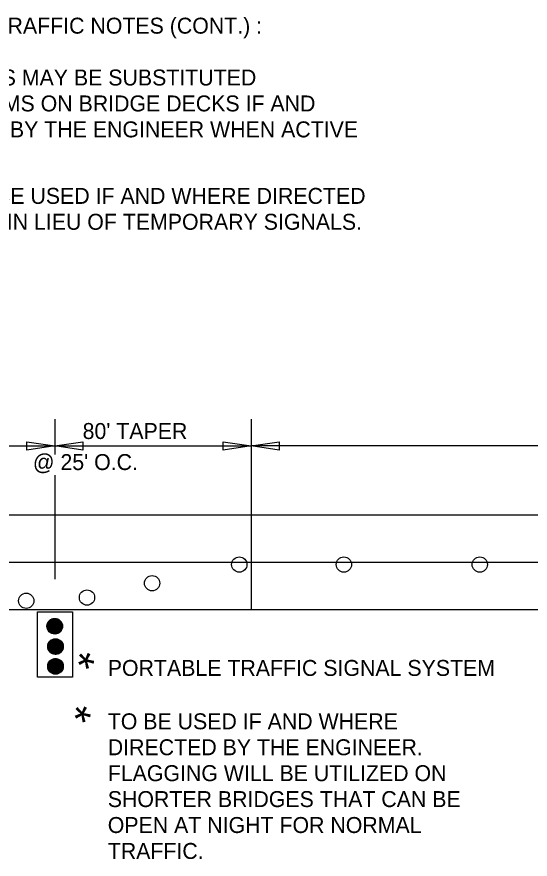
# Model space of a CAD drawing. Extents: x 1927831 to 1930787, y 596452 to 597699.
# Drawn here: x 1928641.1 to 1928834.3, y 597376.1 to 597692.9 of the extents above; entities that cross this region are included whole.
import ezdxf

# ---------------------------------------------------------------- set-up
doc = ezdxf.new("R2010")
doc.units = 0
doc.layers.add('Default', color=7, linetype='Continuous')
doc.layers.add('R_Annotation', color=7, linetype='Continuous')

msp = doc.modelspace()

# ---------------------------------------------------------------- linework, layer by layer
at = {"layer": 'Default'}
for p, q in [((1928655.37, 597541.61), (1928655.37, 597528.34)), ((1928729.31, 597541.61), (1928729.31, 597481.38)), ((1928644.83, 597529.98), (1928644.83, 597533.15)), ((1928644.83, 597533.15), (1928655.37, 597531.57)), ((1928655.37, 597531.57), (1928665.91, 597533.15)), ((1928665.91, 597533.15), (1928665.91, 597529.98)), ((1928718.76, 597529.98), (1928718.76, 597533.15)), ((1928718.76, 597533.15), (1928729.31, 597531.57)), ((1928729.31, 597531.57), (1928739.85, 597533.15)), ((1928739.85, 597533.15), (1928739.85, 597529.98)), ((1928604.7, 597531.57), (1928655.37, 597531.57)), ((1928655.37, 597531.57), (1928644.83, 597529.98)), ((1928655.37, 597531.57), (1928729.31, 597531.57)), ((1928665.91, 597529.98), (1928655.37, 597531.57)), ((1928729.31, 597531.57), (1928718.76, 597529.98)), ((1928739.85, 597529.98), (1928729.31, 597531.57)), ((1929173.7, 597531.57), (1928729.31, 597531.57)), ((1928655.37, 597520.61), (1928655.37, 597481.38)), ((1928729.31, 597510.51), (1928729.31, 597470.05)), ((1928044.85, 597505.58), (1929173.7, 597505.58)), ((1927908.3, 597487.79), (1929173.7, 597487.79)), ((1928044.85, 597470), (1929173.7, 597470)), ((1928652.41, 597463.61), (1928655.49, 597466.69)), ((1928652.41, 597463.79), (1928655.31, 597466.69)), ((1928652.42, 597463.98), (1928655.12, 597466.68)), ((1928652.43, 597463.44), (1928655.66, 597466.67)), ((1928652.44, 597464.18), (1928654.92, 597466.66)), ((1928652.45, 597463.28), (1928655.82, 597466.65)), ((1928652.48, 597463.13), (1928655.97, 597466.62)), ((1928652.49, 597464.41), (1928654.69, 597466.62)), ((1928652.51, 597462.99), (1928656.12, 597466.59)), ((1928652.55, 597462.85), (1928656.26, 597466.55)), ((1928652.56, 597464.66), (1928654.44, 597466.55)), ((1928652.6, 597462.71), (1928656.39, 597466.5)), ((1928652.65, 597462.58), (1928656.52, 597466.45)), ((1928652.67, 597464.95), (1928654.15, 597466.43)), ((1928652.71, 597462.46), (1928656.64, 597466.39)), ((1928652.77, 597462.34), (1928656.76, 597466.33)), ((1928652.84, 597462.23), (1928656.88, 597466.27)), ((1928652.89, 597465.35), (1928653.75, 597466.22)), ((1928652.91, 597462.11), (1928656.99, 597466.19)), ((1928652.98, 597462.01), (1928657.09, 597466.12)), ((1928653.06, 597461.91), (1928657.2, 597466.04)), ((1928653.14, 597461.81), (1928657.29, 597465.96)), ((1928653.23, 597461.71), (1928657.39, 597465.87)), ((1928653.32, 597461.62), (1928657.48, 597465.78)), ((1928653.41, 597461.54), (1928657.57, 597465.69)), ((1928653.51, 597461.45), (1928657.65, 597465.59)), ((1928653.61, 597461.38), (1928657.73, 597465.49)), ((1928653.72, 597461.3), (1928657.8, 597465.38)), ((1928653.83, 597461.23), (1928657.87, 597465.27)), ((1928653.95, 597461.16), (1928657.94, 597465.16)), ((1928654.07, 597461.1), (1928658, 597465.04)), ((1928654.19, 597461.05), (1928658.06, 597464.91)), ((1928654.32, 597460.99), (1928658.11, 597464.78)), ((1928654.45, 597460.95), (1928658.15, 597464.65)), ((1928654.59, 597460.91), (1928658.2, 597464.51)), ((1928654.74, 597460.87), (1928658.23, 597464.36)), ((1928654.89, 597460.84), (1928658.26, 597464.21)), ((1928655.05, 597460.82), (1928658.28, 597464.05)), ((1928655.22, 597460.81), (1928658.29, 597463.88)), ((1928655.4, 597460.81), (1928658.29, 597463.7)), ((1928655.59, 597460.82), (1928658.29, 597463.51)), ((1928655.79, 597460.84), (1928658.26, 597463.31)), ((1928656.02, 597460.88), (1928658.22, 597463.09)), ((1928656.27, 597460.95), (1928658.15, 597462.84)), ((1928656.56, 597461.07), (1928658.04, 597462.54)), ((1928656.96, 597461.28), (1928657.82, 597462.14)), ((1928652.68, 597455.95), (1928655.76, 597459.03)), ((1928652.68, 597456.13), (1928655.58, 597459.03)), ((1928652.69, 597456.32), (1928655.39, 597459.02)), ((1928652.7, 597455.79), (1928655.93, 597459.02)), ((1928652.71, 597456.53), (1928655.19, 597459)), ((1928652.72, 597455.63), (1928656.09, 597458.99)), ((1928652.75, 597455.47), (1928656.24, 597458.97)), ((1928652.76, 597456.75), (1928654.96, 597458.96)), ((1928652.78, 597455.33), (1928656.38, 597458.93)), ((1928652.82, 597455.19), (1928656.52, 597458.89)), ((1928652.83, 597457), (1928654.71, 597458.89)), ((1928652.87, 597455.05), (1928656.66, 597458.84)), ((1928652.92, 597454.92), (1928656.79, 597458.79)), ((1928652.94, 597457.29), (1928654.42, 597458.77)), ((1928652.98, 597454.8), (1928656.91, 597458.73)), ((1928653.04, 597454.68), (1928657.03, 597458.67)), ((1928653.11, 597454.57), (1928657.15, 597458.61)), ((1928653.16, 597457.69), (1928654.02, 597458.56)), ((1928653.18, 597454.46), (1928657.26, 597458.54)), ((1928653.25, 597454.35), (1928657.36, 597458.46)), ((1928653.33, 597454.25), (1928657.46, 597458.38)), ((1928653.41, 597454.15), (1928657.56, 597458.3)), ((1928653.5, 597454.05), (1928657.66, 597458.21)), ((1928653.59, 597453.96), (1928657.75, 597458.12)), ((1928653.68, 597453.88), (1928657.83, 597458.03)), ((1928653.78, 597453.79), (1928657.92, 597457.93)), ((1928653.88, 597453.72), (1928658, 597457.83)), ((1928653.99, 597453.64), (1928658.07, 597457.72)), ((1928654.1, 597453.57), (1928658.14, 597457.61)), ((1928654.22, 597453.51), (1928658.21, 597457.5)), ((1928654.34, 597453.44), (1928658.27, 597457.38)), ((1928654.46, 597453.39), (1928658.32, 597457.25)), ((1928654.59, 597453.34), (1928658.38, 597457.12)), ((1928654.72, 597453.29), (1928658.42, 597456.99)), ((1928654.86, 597453.25), (1928658.46, 597456.85)), ((1928655.01, 597453.21), (1928658.5, 597456.7)), ((1928655.16, 597453.18), (1928658.53, 597456.55)), ((1928655.32, 597453.16), (1928658.55, 597456.39)), ((1928655.49, 597453.15), (1928658.56, 597456.22)), ((1928655.67, 597453.15), (1928658.56, 597456.05)), ((1928655.86, 597453.16), (1928658.56, 597455.86)), ((1928656.06, 597453.18), (1928658.53, 597455.65)), ((1928656.28, 597453.22), (1928658.49, 597455.43)), ((1928656.54, 597453.29), (1928658.42, 597455.18)), ((1928656.83, 597453.41), (1928658.31, 597454.88)), ((1928657.23, 597453.62), (1928658.09, 597454.48)), ((1928652.68, 597448.61), (1928655.66, 597451.59)), ((1928652.68, 597448.8), (1928655.48, 597451.59)), ((1928652.69, 597448.44), (1928655.83, 597451.58)), ((1928652.7, 597448.99), (1928655.28, 597451.57)), ((1928652.71, 597448.27), (1928656, 597451.57)), ((1928652.73, 597448.12), (1928656.15, 597451.54)), ((1928652.73, 597449.21), (1928655.06, 597451.54)), ((1928652.76, 597447.97), (1928656.3, 597451.51)), ((1928652.79, 597449.45), (1928654.83, 597451.48)), ((1928652.8, 597447.83), (1928656.45, 597451.47)), ((1928652.84, 597447.69), (1928656.58, 597451.43)), ((1928652.88, 597449.72), (1928654.56, 597451.39)), ((1928652.89, 597447.56), (1928656.72, 597451.38)), ((1928652.95, 597447.43), (1928656.84, 597451.33)), ((1928653.01, 597447.31), (1928656.96, 597451.27)), ((1928653.04, 597450.05), (1928654.22, 597451.23)), ((1928653.07, 597447.19), (1928657.08, 597451.2)), ((1928653.14, 597447.08), (1928657.2, 597451.14)), ((1928653.21, 597446.97), (1928657.3, 597451.06)), ((1928653.29, 597446.86), (1928657.41, 597450.99)), ((1928653.37, 597446.76), (1928657.51, 597450.91)), ((1928653.45, 597446.67), (1928657.61, 597450.82)), ((1928653.54, 597446.57), (1928657.7, 597450.73)), ((1928653.63, 597446.49), (1928657.79, 597450.64)), ((1928653.73, 597446.4), (1928657.87, 597450.55)), ((1928653.83, 597446.32), (1928657.95, 597450.45)), ((1928653.93, 597446.24), (1928658.03, 597450.34)), ((1928654.04, 597446.17), (1928658.1, 597450.23)), ((1928654.15, 597446.1), (1928658.17, 597450.12)), ((1928654.27, 597446.04), (1928658.23, 597450)), ((1928654.39, 597445.98), (1928658.29, 597449.88)), ((1928654.65, 597445.87), (1928658.4, 597449.63)), ((1928654.78, 597445.83), (1928658.44, 597449.49)), ((1928654.93, 597445.79), (1928658.48, 597449.35)), ((1928655.07, 597445.76), (1928658.51, 597449.2)), ((1928655.23, 597445.73), (1928658.54, 597449.04)), ((1928655.39, 597445.72), (1928658.56, 597448.88)), ((1928655.57, 597445.71), (1928658.56, 597448.71)), ((1928655.75, 597445.71), (1928658.56, 597448.52)), ((1928655.95, 597445.73), (1928658.55, 597448.33)), ((1928656.16, 597445.76), (1928658.52, 597448.12)), ((1928656.39, 597445.81), (1928658.46, 597447.88)), ((1928656.66, 597445.9), (1928658.38, 597447.61)), ((1928656.99, 597446.04), (1928658.23, 597447.29)), ((1928657.56, 597446.44), (1928657.84, 597446.71))]:
    msp.add_line(p, q, dxfattribs=at)
msp.add_lwpolyline([(1928648.78, 597469.1), (1928662.07, 597469.1), (1928662.07, 597444.57), (1928648.78, 597444.57)], close=True, dxfattribs=at)
for centre, radius in [((1928724.81, 597486.95), 2.88), ((1928764.17, 597486.95), 2.88), ((1928815.34, 597486.95), 2.88), ((1928691.97, 597479.91), 2.88), ((1928644.59, 597473.3), 2.88), ((1928667.47, 597474.54), 2.88), ((1928655.35, 597463.75), 2.94), ((1928655.62, 597456.09), 2.94), ((1928655.62, 597448.65), 2.94)]:
    msp.add_circle(centre, radius, dxfattribs=at)

# ---------------------------------------------------------------- texts
for s, p in [("80' TAPER", (1928665.82, 597534.16)), ("@ 25' O.C.", (1928647.1, 597522.48)), ('PORTABLE TRAFFIC SIGNAL SYSTEM', (1928675.29, 597445.05))]:
    msp.add_text(s, height=6, rotation=360, dxfattribs=at).set_placement(p)
at = {"layer": 'R_Annotation'}
for s, height, rotation, p in [('MAINTENANCE OF TRAFFIC NOTES (CONT.) :', 6, 360, (1928558.66, 597686.62)), ('5. VERTICAL PANELS MAY BE SUBSTITUTED', 6, 360, (1928558.66, 597667.12)), ('  FOR TRAFFIC DRUMS ON BRIDGE DECKS IF AND', 6, 360, (1928558.66, 597657.37)), ('  WHERE DIRECTED BY THE ENGINEER WHEN ACTIVE', 6, 360, (1928558.66, 597647.62)), ('6.  FLAGGING WILL BE USED IF AND WHERE DIRECTED', 6, 360, (1928557.46, 597622.6)), ('  BY THE ENGINEER IN LIEU OF TEMPORARY SIGNALS.', 6, 360, (1928557.46, 597612.85)), ('*', 12, 45, (1928671.07, 597442.43)), ('*', 12, 45, (1928669.75, 597422.28)), ('TO BE USED IF AND WHERE', 6, 360, (1928675.29, 597424.97)), ('DIRECTED BY THE ENGINEER.', 6, 360, (1928675.29, 597415.22)), ('FLAGGING WILL BE UTILIZED ON', 6, 360, (1928675.29, 597405.47)), ('SHORTER BRIDGES THAT CAN BE ', 6, 360, (1928675.29, 597395.72)), ('OPEN AT NIGHT FOR NORMAL ', 6, 360, (1928675.29, 597385.97)), ('TRAFFIC.', 6, 360, (1928675.29, 597376.22))]:
    msp.add_text(s, height=height, rotation=rotation, dxfattribs=at).set_placement(p)

doc.saveas('drawing.dxf')
